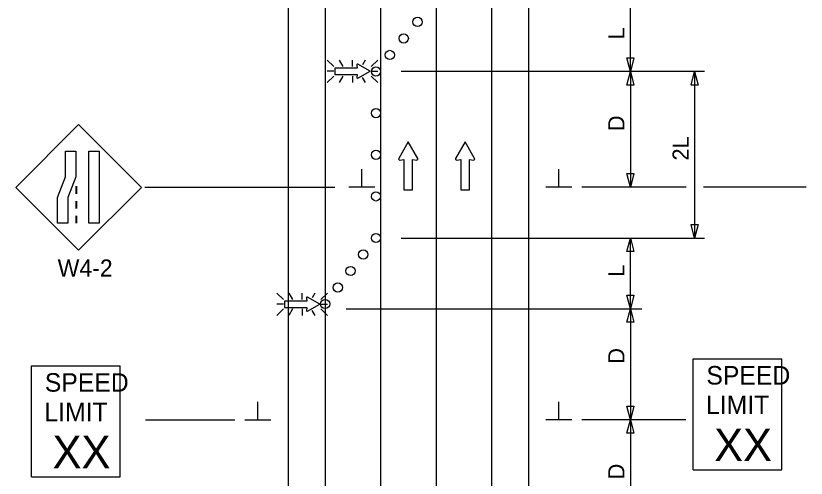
# Model space of a CAD drawing. Extents: x 16727 to 18475, y 5729 to 6909.
# Drawn here: x 16783.5 to 17125.3, y 6352.6 to 6552.5 of the extents above; entities that cross this region are included whole.
import ezdxf

# ---------------------------------------------------------------- set-up
doc = ezdxf.new("R2010")
doc.units = 0
for name, color, linetype in [('ALI_LEGAL_EX', 7, 'Continuous'), ('MT_SCRATCH_LEVEL_E', 7, 'Continuous'), ('PAVT_EDGE_EX', 7, 'Continuous'), ('TRAFFIC_SIGNS_PR', 7, 'Continuous'), ('TYPICAL_TEXT_DIMEN_PR', 7, 'Continuous')]:
    doc.layers.add(name, color=color, linetype=linetype)

msp = doc.modelspace()

# ---------------------------------------------------------------- linework, layer by layer
at = {"layer": 'ALI_LEGAL_EX'}
for p, q in [((16941.23, 6891.16), (16941.23, 6061.98)), ((16965.23, 6891.16), (16965.23, 6061.98)), ((16965.23, 6891.16), (16965.23, 6061.98))]:
    msp.add_line(p, q, dxfattribs=at)
for points in [[(16941.23, 6491.16), (16941.23, 6466.16)], [(16965.23, 6491.16), (16965.23, 6466.16)], [(16941.23, 6391.16), (16941.23, 6366.16)], [(16965.23, 6391.16), (16965.23, 6366.16)]]:
    msp.add_lwpolyline(points, dxfattribs=at)
at = {"layer": 'MT_SCRATCH_LEVEL_E'}
for p, q in [((16953.2, 6498.06), (16949.09, 6490.82)), ((16953.2, 6498.06), (16949.09, 6490.82)), ((16957.35, 6490.82), (16953.2, 6498.06)), ((16957.35, 6490.82), (16953.2, 6498.06)), ((16977.76, 6498.06), (16973.65, 6490.82)), ((16977.76, 6498.06), (16973.65, 6490.82)), ((16981.9, 6490.82), (16977.76, 6498.06)), ((16981.9, 6490.82), (16977.76, 6498.06)), ((16949.57, 6490.14), (16951.35, 6490.45)), ((16949.57, 6490.14), (16951.35, 6490.45)), ((16951.35, 6490.45), (16951.35, 6477.2)), ((16951.35, 6490.45), (16951.35, 6477.2)), ((16955.09, 6477.2), (16955.09, 6490.45)), ((16955.09, 6490.45), (16956.87, 6490.14)), ((16955.09, 6477.2), (16955.09, 6490.45)), ((16955.09, 6490.45), (16956.87, 6490.14)), ((16974.13, 6490.14), (16975.9, 6490.45)), ((16974.13, 6490.14), (16975.9, 6490.45)), ((16975.9, 6490.45), (16975.9, 6477.2)), ((16975.9, 6490.45), (16975.9, 6477.2)), ((16979.65, 6477.2), (16979.65, 6490.45)), ((16979.65, 6490.45), (16981.42, 6490.14)), ((16979.65, 6477.2), (16979.65, 6490.45)), ((16979.65, 6490.45), (16981.42, 6490.14)), ((16951.35, 6477.2), (16955.09, 6477.2)), ((16951.35, 6477.2), (16955.09, 6477.2)), ((16975.9, 6477.2), (16979.65, 6477.2)), ((16975.9, 6477.2), (16979.65, 6477.2))]:
    msp.add_line(p, q, dxfattribs=at)
for centre, start, end in [((16949.49, 6490.6), 150.4248, 279.9638), ((16949.49, 6490.6), 150.4248, 279.9638), ((16956.94, 6490.6), 260.0362, 29.7731), ((16956.94, 6490.6), 260.0362, 29.7731), ((16974.05, 6490.6), 150.4248, 279.9638), ((16974.05, 6490.6), 150.4248, 279.9638), ((16981.49, 6490.6), 260.0362, 29.7731), ((16981.49, 6490.6), 260.0362, 29.7731)]:
    msp.add_arc(centre, 0.463, start, end, dxfattribs=at)
at = {"layer": 'PAVT_EDGE_EX'}
for p, q in [((16901.23, 6891.16), (16901.23, 6061.98)), ((16917.23, 6891.16), (16917.23, 6061.98)), ((16917.23, 6891.16), (16917.23, 6061.98)), ((16989.23, 6891.16), (16989.23, 6061.98)), ((17005.23, 6891.16), (17005.23, 6061.98))]:
    msp.add_line(p, q, dxfattribs=at)
at = {"layer": 'TRAFFIC_SIGNS_PR'}
for p, q in [((16921.01, 6530.55), (16918.18, 6533.37)), ((16923.3, 6533.37), (16924.93, 6530.55)), ((16929.09, 6530.55), (16929.09, 6533.37)), ((16934.56, 6533.37), (16933.35, 6531.27)), ((16939.99, 6533.36), (16937.17, 6530.55)), ((16921.01, 6528.52), (16918.18, 6528.52)), ((16937.17, 6528.52), (16939.99, 6528.52)), ((16921.01, 6526.48), (16918.18, 6523.66)), ((16924.96, 6526.48), (16923.33, 6523.66)), ((16929.09, 6526.48), (16929.09, 6523.66)), ((16933.27, 6525.85), (16934.53, 6523.66)), ((16939.99, 6523.66), (16937.17, 6526.48)), ((16810.64, 6505.46), (16783.48, 6478.31)), ((16837.79, 6478.31), (16810.64, 6505.46)), ((16783.48, 6478.31), (16810.64, 6451.15)), ((16809.39, 6478.8), (16809.39, 6475.6)), ((16809.79, 6478.8), (16809.79, 6475.6)), ((16810.64, 6451.15), (16837.79, 6478.31)), ((16809.39, 6472.4), (16809.39, 6469.2)), ((16809.79, 6472.4), (16809.79, 6469.2)), ((16809.39, 6466), (16809.39, 6462.8)), ((16809.79, 6466), (16809.79, 6462.8)), ((16899.25, 6429.83), (16896.43, 6432.65)), ((16901.55, 6432.65), (16903.17, 6429.83)), ((16907.33, 6429.83), (16907.33, 6432.65)), ((16912.8, 6432.65), (16911.6, 6430.56)), ((16918.24, 6432.65), (16915.42, 6429.83)), ((16899.25, 6427.8), (16896.43, 6427.8)), ((16899.25, 6425.77), (16896.43, 6422.94)), ((16903.2, 6425.77), (16901.57, 6422.94)), ((16907.33, 6425.77), (16907.33, 6422.94)), ((16915.42, 6427.8), (16918.24, 6427.8)), ((16918.24, 6422.95), (16915.42, 6425.77)), ((16911.52, 6425.13), (16912.78, 6422.94)), ((17076.34, 6404.23), (17114.74, 6404.23)), ((17076.34, 6356.23), (17076.34, 6404.23)), ((17114.74, 6356.23), (17114.74, 6404.23)), ((16790.26, 6401.15), (16828.66, 6401.15)), ((16790.26, 6353.15), (16790.26, 6401.15)), ((16828.66, 6353.15), (16828.66, 6401.15)), ((17076.34, 6356.23), (17114.74, 6356.23)), ((16790.26, 6353.15), (16828.66, 6353.15))]:
    msp.add_line(p, q, dxfattribs=at)
for points in [[(16930.92, 6531.2), (16931.15, 6529.9), (16921.42, 6529.9), (16921.42, 6527.16), (16931.15, 6527.16), (16930.92, 6525.85)], [(16931.42, 6525.5), (16936.73, 6528.52), (16931.42, 6531.56)], [(16909.16, 6430.48), (16909.39, 6429.18), (16899.67, 6429.18), (16899.67, 6426.44), (16909.39, 6426.44), (16909.16, 6425.14)], [(16909.66, 6424.78), (16914.97, 6427.8), (16909.66, 6430.84)]]:
    msp.add_lwpolyline(points, dxfattribs=at)
for points in [[(16809.39, 6494.04), (16809.39, 6482.86), (16806.04, 6473.98), (16806.04, 6462.8), (16801.55, 6462.8), (16801.55, 6473.98), (16804.9, 6482.86), (16804.9, 6494.04)], [(16819.52, 6494.04), (16819.52, 6462.8), (16815.03, 6462.8), (16815.03, 6494.04)]]:
    msp.add_lwpolyline(points, close=True, dxfattribs=at)
for centre in [(16957.23, 6549.87), (16951.23, 6542.73), (16945.23, 6535.59), (16939.23, 6528.44), (16939.23, 6510.44), (16939.23, 6492.44), (16939.23, 6474.44), (16939.23, 6456.44), (16933.73, 6449.31), (16928.24, 6442.19), (16922.74, 6435.06), (16917.24, 6427.93)]:
    msp.add_circle(centre, 2, dxfattribs=at)
for centre, start, end in [((16931.25, 6531.26), 61.4833, 189.9593), ((16931.25, 6525.8), 170.7308, 298.8916), ((16909.5, 6430.54), 61.4833, 189.9593), ((16909.5, 6425.08), 170.7308, 298.8916)]:
    msp.add_arc(centre, 0.341, start, end, dxfattribs=at)
at = {"layer": 'TYPICAL_TEXT_DIMEN_PR'}
for p, q in [((17049.23, 6528.44), (17049.23, 6559.01)), ((17049.23, 6528.44), (17047.66, 6534.31)), ((17047.66, 6534.31), (17049.23, 6534.31)), ((17049.23, 6534.31), (17050.8, 6534.31)), ((17050.8, 6534.31), (17049.23, 6528.44)), ((17081.27, 6528.44), (16950.13, 6528.44)), ((17047.66, 6522.58), (17049.23, 6528.44)), ((17049.23, 6528.44), (17049.23, 6478.44)), ((17049.23, 6528.44), (17050.8, 6522.58)), ((17075.47, 6522.58), (17077.04, 6528.44)), ((17077.04, 6528.44), (17078.61, 6522.58)), ((17077.04, 6528.44), (17077.04, 6456.44)), ((17049.23, 6522.58), (17047.66, 6522.58)), ((17050.8, 6522.58), (17049.23, 6522.58)), ((17077.04, 6522.58), (17075.47, 6522.58)), ((17078.61, 6522.58), (17077.04, 6522.58)), ((16933.16, 6478.44), (16933.16, 6486.23)), ((17018.35, 6478.44), (17018.35, 6486.23)), ((17049.23, 6478.44), (17047.66, 6484.31)), ((17047.66, 6484.31), (17049.23, 6484.31)), ((17049.23, 6484.31), (17050.8, 6484.31)), ((17050.8, 6484.31), (17049.23, 6478.44)), ((17077.04, 6483.31), (17077.04, 6479.55)), ((16839.23, 6478.44), (16921.43, 6478.44)), ((16938.78, 6478.44), (16927.53, 6478.44)), ((17023.98, 6478.44), (17012.73, 6478.44)), ((17073.35, 6478.44), (17028.23, 6478.44)), ((17125.27, 6478.44), (17080.85, 6478.44)), ((17077.04, 6456.44), (17075.47, 6462.31)), ((17075.47, 6462.31), (17077.04, 6462.31)), ((17077.04, 6462.31), (17078.61, 6462.31)), ((17078.61, 6462.31), (17077.04, 6456.44)), ((16950.13, 6456.44), (17081.27, 6456.44)), ((17047.66, 6450.58), (17049.23, 6456.44)), ((17049.23, 6425.88), (17049.23, 6456.44)), ((17049.23, 6456.44), (17050.8, 6450.58)), ((17049.23, 6450.58), (17047.66, 6450.58)), ((17050.8, 6450.58), (17049.23, 6450.58)), ((17049.23, 6425.88), (17047.66, 6431.74)), ((17047.66, 6431.74), (17049.23, 6431.74)), ((17049.23, 6431.74), (17050.8, 6431.74)), ((17050.8, 6431.74), (17049.23, 6425.88)), ((16926.39, 6425.88), (17054.23, 6425.88)), ((17047.66, 6420.02), (17049.23, 6425.88)), ((17049.23, 6425.88), (17049.23, 6377.89)), ((17049.23, 6425.88), (17050.8, 6420.02)), ((17049.23, 6420.02), (17047.66, 6420.02)), ((17050.8, 6420.02), (17049.23, 6420.02)), ((16888.1, 6377.89), (16888.1, 6385.67)), ((17018.35, 6377.89), (17018.35, 6385.67)), ((17049.23, 6377.89), (17047.66, 6383.75)), ((17047.66, 6383.75), (17049.23, 6383.75)), ((17049.23, 6383.75), (17050.8, 6383.75)), ((17050.8, 6383.75), (17049.23, 6377.89)), ((16839.57, 6377.89), (16878.23, 6377.89)), ((16882.48, 6377.89), (16893.73, 6377.89)), ((17023.98, 6377.89), (17012.73, 6377.89)), ((17073.29, 6377.89), (17028.23, 6377.89)), ((17047.66, 6372.03), (17049.23, 6377.89)), ((17049.23, 6377.89), (17049.23, 6327.89)), ((17049.23, 6377.89), (17050.8, 6372.03)), ((17049.23, 6372.03), (17047.66, 6372.03)), ((17050.8, 6372.03), (17049.23, 6372.03))]:
    msp.add_line(p, q, dxfattribs=at)

# ---------------------------------------------------------------- texts
at = {"layer": 'TRAFFIC_SIGNS_PR'}
for s, height, p in [('W4-2', 7.44, (16801.59, 6439.72)), ('SPEED', 8, (17082.11, 6393.09)), ('SPEED', 8, (16796.03, 6390.01)), ('LIMIT', 8, (17081.95, 6380.29)), ('LIMIT', 8, (16795.87, 6377.21)), ('XX', 14.031, (17085.46, 6359.99)), ('XX', 14.031, (16799.38, 6356.9))]:
    msp.add_text(s, height=height, dxfattribs=at).set_placement(p)
at = {"layer": 'TYPICAL_TEXT_DIMEN_PR'}
for s, p in [('L', (17046.67, 6542.3)), ('D', (17046.67, 6502.66)), ('2L', (17074.48, 6489.95)), ('L', (17046.67, 6439.74)), ('D', (17046.67, 6402.11)), ('D', (17046.67, 6352.11))]:
    msp.add_text(s, height=7, rotation=90, dxfattribs=at).set_placement(p)

doc.saveas('drawing.dxf')
